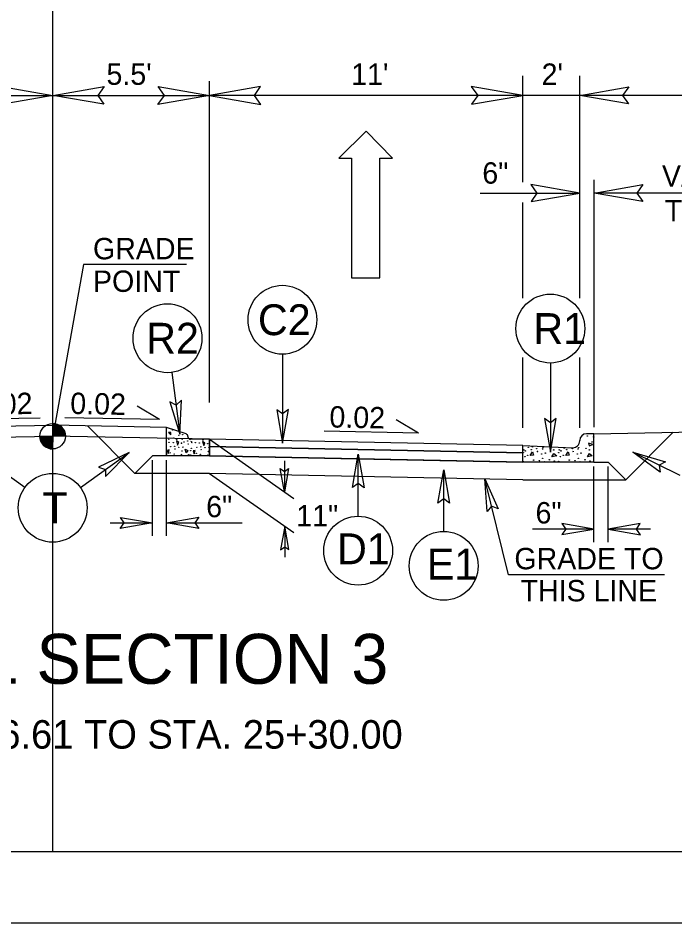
# Model space of a CAD drawing. Extents: x 1487909 to 1489267, y 497866 to 499814.
# Drawn here: x 1488973.75 to 1488996.8, y 498227.52 to 498259.26 of the extents above; entities that cross this region are included whole.
import ezdxf

# ---------------------------------------------------------------- set-up
doc = ezdxf.new("R2010")
doc.units = 0
for name, color, linetype in [('Old_Level_10', 7, 'Continuous'), ('Prop Dimension', 7, 'Continuous'), ('Prop Dimension Text', 7, 'Continuous'), ('Prop Lane Arrow CELL', 7, 'Continuous'), ('Prop Shade Light', 7, 'Continuous'), ('Prop Terminator CELL', 7, 'Continuous'), ('Scratch_Level_1', 7, 'Continuous'), ('Sheet Plot Border Outside CELL', 7, 'Continuous'), ('Sheet Typical CELL', 7, 'Continuous'), ('Typical Curb CELL', 7, 'Continuous'), ('Typical Detail Wedge2 CELL', 7, 'Continuous'), ('Typical Grade Point Symbol CELL', 7, 'Continuous'), ('Typical Hinge Slope Arterial CELL', 7, 'Continuous'), ('Typical ID Circle CELL', 7, 'Continuous'), ('Typical Pavement Slope CELL', 7, 'Continuous'), ('Typical Pavement Slope Information CELL', 7, 'Continuous'), ('Typical Terminator CELL', 7, 'Continuous'), ('Typical Text Grade Point CELL', 7, 'Continuous'), ('Typical Text ID Circle CELL', 7, 'Continuous')]:
    doc.layers.add(name, color=color, linetype=linetype)

msp = doc.modelspace()

# ---------------------------------------------------------------- linework, layer by layer
at = {"layer": 'Old_Level_10'}
for p, q in [((1488980.464, 498244.233), (1488980.464, 498243.899)), ((1488991.464, 498244.013), (1488980.464, 498244.233)), ((1488980.464, 498244.233), (1488980.464, 498244.233)), ((1488991.464, 498243.679), (1488991.464, 498244.013)), ((1488980.464, 498243.899), (1488987.964, 498243.749)), ((1488987.964, 498243.749), (1488991.464, 498243.679))]:
    msp.add_line(p, q, dxfattribs=at)
at = {"layer": 'Prop Dimension'}
for p, q in [((1488974.964, 498243.638), (1488974.964, 498259.111)), ((1488980.464, 498245.779), (1488980.464, 498257.045)), ((1488991.464, 498253.503), (1488991.464, 498257.235)), ((1488993.463, 498249.434), (1488993.463, 498257.235)), ((1488969.464, 498256.545), (1488974.964, 498256.545)), ((1488974.964, 498256.545), (1488980.464, 498256.545)), ((1488991.464, 498256.545), (1488980.464, 498256.545)), ((1488993.464, 498256.545), (1488991.464, 498256.545)), ((1489012.964, 498256.545), (1488993.464, 498256.545)), ((1488993.964, 498244.905), (1488993.964, 498253.586)), ((1488989.969, 498253.115), (1488993.464, 498253.115)), ((1489001.964, 498253.115), (1488993.964, 498253.115)), ((1488991.463, 498249.434), (1488991.463, 498252.793)), ((1488991.463, 498244.883), (1488991.463, 498247.353)), ((1488993.463, 498244.883), (1488993.463, 498247.353)), ((1488978.464, 498241.093), (1488978.464, 498243.747)), ((1488978.964, 498241.093), (1488978.964, 498243.747)), ((1488993.963, 498240.873), (1488993.963, 498243.527)), ((1488994.463, 498240.873), (1488994.463, 498243.527)), ((1488990.963, 498239.729), (1488990.13, 498243.093)), ((1488976.977, 498241.553), (1488978.464, 498241.553)), ((1488978.964, 498241.553), (1488981.612, 498241.553)), ((1488993.963, 498241.333), (1488991.802, 498241.333)), ((1488995.95, 498241.333), (1488994.463, 498241.333)), ((1488996.436, 498239.729), (1488990.963, 498239.729))]:
    msp.add_line(p, q, dxfattribs=at)
at = {"layer": 'Prop Dimension Text'}
for p, q in [((1488976.051, 498250.615), (1488974.964, 498244.593)), ((1488979.666, 498250.615), (1488976.051, 498250.615))]:
    msp.add_line(p, q, dxfattribs=at)
at = {"layer": 'Prop Lane Arrow CELL'}
for p, q in [((1488985.962, 498255.291), (1488985.002, 498254.346)), ((1488986.892, 498254.346), (1488985.962, 498255.291)), ((1488985.002, 498254.346), (1488985.452, 498254.346)), ((1488985.452, 498254.346), (1488985.452, 498250.146)), ((1488986.442, 498250.146), (1488986.442, 498254.346)), ((1488986.442, 498254.346), (1488986.892, 498254.346)), ((1488985.452, 498250.146), (1488986.442, 498250.146))]:
    msp.add_line(p, q, dxfattribs=at)
at = {"layer": 'Prop Shade Light'}
for p, q in [((1488991.464, 498244.263), (1488980.464, 498244.483)), ((1488980.464, 498244.483), (1488980.464, 498244.233)), ((1488991.464, 498244.013), (1488991.464, 498244.263)), ((1488980.464, 498244.233), (1488991.464, 498244.013))]:
    msp.add_line(p, q, dxfattribs=at)
at = {"layer": 'Prop Terminator CELL'}
for points in [[(1488973.164, 498256.855), (1488974.964, 498256.545), (1488973.154, 498256.225), (1488973.384, 498256.545)], [(1488976.764, 498256.235), (1488974.964, 498256.545), (1488976.774, 498256.865), (1488976.544, 498256.545)], [(1488978.664, 498256.855), (1488980.464, 498256.545), (1488978.654, 498256.225), (1488978.884, 498256.545)], [(1488982.264, 498256.855), (1488980.464, 498256.545), (1488982.274, 498256.225), (1488982.044, 498256.545)], [(1488989.664, 498256.235), (1488991.464, 498256.545), (1488989.654, 498256.865), (1488989.884, 498256.545)], [(1488995.174, 498256.25), (1488993.464, 498256.545), (1488995.183, 498256.849), (1488994.965, 498256.545)], [(1488991.754, 498252.82), (1488993.464, 498253.115), (1488991.744, 498253.419), (1488991.963, 498253.115)], [(1488995.674, 498252.82), (1488993.964, 498253.115), (1488995.683, 498253.419), (1488995.465, 498253.115)], [(1488990.212, 498241.954), (1488990.13, 498243.093), (1488990.596, 498242.043), (1488990.367, 498242.134)], [(1488977.339, 498241.746), (1488978.464, 498241.553), (1488977.333, 498241.353), (1488977.476, 498241.553)], [(1488980.089, 498241.359), (1488978.964, 498241.553), (1488980.095, 498241.753), (1488979.951, 498241.553)], [(1488992.838, 498241.139), (1488993.963, 498241.333), (1488992.832, 498241.533), (1488992.976, 498241.333)], [(1488995.588, 498241.526), (1488994.463, 498241.333), (1488995.594, 498241.133), (1488995.451, 498241.333)]]:
    msp.add_lwpolyline(points, close=True, dxfattribs=at)
at = {"layer": 'Scratch_Level_1'}
msp.add_line((1488974.964, 498230.02), (1488974.964, 498335.02), dxfattribs=at)
at = {"layer": 'Sheet Plot Border Outside CELL'}
msp.add_lwpolyline([(1489051.664, 498337.52), (1488883.264, 498337.52), (1488883.264, 498227.52), (1489051.664, 498227.52)], close=True, dxfattribs=at)
at = {"layer": 'Sheet Typical CELL'}
msp.add_lwpolyline([(1489049.964, 498335.02), (1488899.964, 498335.02), (1488899.964, 498230.02), (1489049.964, 498230.02)], close=True, dxfattribs=at)
at = {"layer": 'Typical Curb CELL'}
for p, q in [((1488978.964, 498243.899), (1488978.964, 498244.899)), ((1488979.65, 498244.671), (1488978.964, 498244.899)), ((1488979.111, 498244.728), (1488979.025, 498244.728)), ((1488979.025, 498244.728), (1488979.106, 498244.641)), ((1488979.106, 498244.641), (1488979.111, 498244.728)), ((1488979.714, 498244.576), (1488979.714, 498244.582)), ((1488993.963, 498244.679), (1488993.703, 498244.679)), ((1488993.963, 498243.679), (1488993.963, 498244.679)), ((1488979.309, 498244.425), (1488979.35, 498244.275)), ((1488979.391, 498244.366), (1488979.309, 498244.425)), ((1488979.35, 498244.275), (1488979.391, 498244.366)), ((1488980.464, 498244.483), (1488979.807, 498244.483)), ((1488980.228, 498244.409), (1488980.27, 498244.261)), ((1488980.31, 498244.351), (1488980.228, 498244.409)), ((1488980.27, 498244.261), (1488980.31, 498244.351)), ((1488980.464, 498244.483), (1488980.464, 498243.899)), ((1488980.464, 498243.899), (1488980.464, 498244.476)), ((1488991.464, 498243.679), (1488991.464, 498244.263)), ((1488991.464, 498244.263), (1488993.214, 498244.19)), ((1488993.463, 498244.429), (1488993.463, 498244.44)), ((1488993.773, 498244.346), (1488993.789, 498244.255)), ((1488993.927, 498244.301), (1488993.773, 498244.346)), ((1488993.789, 498244.255), (1488993.927, 498244.301)), ((1488979.052, 498244.109), (1488978.979, 498244.095)), ((1488978.979, 498244.095), (1488979.016, 498243.986)), ((1488979.016, 498243.986), (1488979.052, 498244.109)), ((1488979.617, 498244.136), (1488979.707, 498244.086)), ((1488979.648, 498244.005), (1488979.617, 498244.136)), ((1488979.707, 498244.086), (1488979.648, 498244.005)), ((1488979.971, 498244.093), (1488979.899, 498244.079)), ((1488979.899, 498244.079), (1488979.935, 498243.971)), ((1488979.935, 498243.971), (1488979.971, 498244.093)), ((1488991.724, 498243.919), (1488991.81, 498244.039)), ((1488991.81, 498244.039), (1488991.845, 498243.925)), ((1488992.489, 498243.868), (1488992.552, 498243.982)), ((1488992.552, 498243.982), (1488992.655, 498243.907)), ((1488992.974, 498243.919), (1488993.059, 498244.039)), ((1488993.059, 498244.039), (1488993.094, 498243.925)), ((1488993.738, 498243.868), (1488993.801, 498243.982)), ((1488993.801, 498243.982), (1488993.904, 498243.907)), ((1488980.464, 498243.899), (1488978.964, 498243.899)), ((1488993.963, 498243.679), (1488991.464, 498243.679)), ((1488991.845, 498243.925), (1488991.724, 498243.919)), ((1488992.655, 498243.907), (1488992.489, 498243.868)), ((1488993.094, 498243.925), (1488992.974, 498243.919)), ((1488993.904, 498243.907), (1488993.738, 498243.868))]:
    msp.add_line(p, q, dxfattribs=at)
for centre, radius in [((1488979.174, 498244.813), 0.00635), ((1488979.391, 498244.624), 0.00635), ((1488979.526, 498244.646), 0.00635), ((1488993.733, 498244.603), 0.00802), ((1488993.95, 498244.569), 0.00802), ((1488979.039, 498244.488), 0.00635), ((1488979.047, 498244.38), 0.00635), ((1488979.197, 498244.366), 0.00635), ((1488979.201, 498244.529), 0.00635), ((1488979.319, 498244.479), 0.00635), ((1488979.486, 498244.348), 0.00635), ((1488979.508, 498244.484), 0.00635), ((1488979.576, 498244.393), 0.00635), ((1488979.698, 498244.42), 0.00635), ((1488979.721, 498244.321), 0.00635), ((1488979.834, 498244.398), 0.00635), ((1488979.849, 498244.369), 0.00635), ((1488979.967, 498244.364), 0.00635), ((1488980.116, 498244.351), 0.00635), ((1488980.238, 498244.463), 0.00635), ((1488980.405, 498244.332), 0.00635), ((1488993.898, 498244.387), 0.00802), ((1488979.084, 498244.009), 0.00635), ((1488979.106, 498244.222), 0.00635), ((1488979.228, 498243.969), 0.00635), ((1488979.242, 498244.235), 0.00635), ((1488979.255, 498244.14), 0.00635), ((1488979.391, 498244.204), 0.00635), ((1488979.49, 498243.951), 0.00635), ((1488979.504, 498244.073), 0.00635), ((1488979.535, 498244.208), 0.00635), ((1488979.734, 498243.946), 0.00635), ((1488979.811, 498244.086), 0.00635), ((1488979.811, 498243.933), 0.00635), ((1488979.827, 498244.165), 0.00635), ((1488980.003, 498243.994), 0.00635), ((1488980.025, 498244.206), 0.00635), ((1488980.147, 498243.953), 0.00635), ((1488980.161, 498244.22), 0.00635), ((1488980.174, 498244.125), 0.00635), ((1488980.31, 498244.188), 0.00635), ((1488980.409, 498243.935), 0.00635), ((1488980.423, 498244.057), 0.00635), ((1488980.455, 498244.192), 0.00635), ((1488991.48, 498244.016), 0.00802), ((1488991.497, 498244.113), 0.00802), ((1488991.553, 498244.079), 0.00802), ((1488991.662, 498244.204), 0.00802), ((1488991.759, 498244.119), 0.00802), ((1488991.804, 498244.221), 0.00802), ((1488991.953, 498244.158), 0.00802), ((1488991.981, 498244.056), 0.00802), ((1488992.13, 498243.971), 0.00802), ((1488992.158, 498244.142), 0.00802), ((1488992.175, 498244.192), 0.00802), ((1488992.256, 498243.999), 0.00802), ((1488992.432, 498244.164), 0.00802), ((1488992.552, 498244.113), 0.00802), ((1488992.729, 498244.016), 0.00802), ((1488992.746, 498244.113), 0.00802), ((1488992.802, 498244.079), 0.00802), ((1488992.911, 498244.173), 0.00802), ((1488993.008, 498244.119), 0.00802), ((1488993.202, 498244.158), 0.00802), ((1488993.23, 498244.056), 0.00802), ((1488993.379, 498243.971), 0.00802), ((1488993.407, 498244.142), 0.00802), ((1488993.425, 498244.192), 0.00802), ((1488993.505, 498243.999), 0.00802), ((1488993.681, 498244.164), 0.00802), ((1488993.801, 498244.113), 0.00802), ((1488991.474, 498243.708), 0.00802), ((1488991.537, 498243.874), 0.00802), ((1488991.633, 498243.919), 0.00802), ((1488991.685, 498243.685), 0.00802), ((1488991.844, 498243.754), 0.00802), ((1488992.05, 498243.731), 0.00802), ((1488992.164, 498243.817), 0.00802), ((1488992.221, 498243.702), 0.00802), ((1488992.398, 498243.765), 0.00802), ((1488992.569, 498243.725), 0.00802), ((1488992.723, 498243.708), 0.00802), ((1488992.786, 498243.874), 0.00802), ((1488992.882, 498243.919), 0.00802), ((1488992.934, 498243.685), 0.00802), ((1488993.093, 498243.754), 0.00802), ((1488993.299, 498243.731), 0.00802), ((1488993.413, 498243.817), 0.00802), ((1488993.47, 498243.702), 0.00802), ((1488993.647, 498243.765), 0.00802), ((1488993.818, 498243.725), 0.00802)]:
    msp.add_circle(centre, radius, dxfattribs=at)
for centre, radius, start, end in [((1488979.62, 498244.582), 0.0937, 360, 71.565), ((1488979.807, 498244.576), 0.0937, 180, 270), ((1488993.703, 498244.44), 0.24, 90, 180), ((1488993.224, 498244.429), 0.24, 267.6155, 0), ((1488978.998, 498243.905), 0.00635, 27.0386, 154.2416)]:
    msp.add_arc(centre, radius, start, end, dxfattribs=at)
at = {"layer": 'Typical Detail Wedge2 CELL'}
for p, q in [((1488980.464, 498244.483), (1488983.428, 498242.407)), ((1488983.096, 498243.723), (1488983.096, 498242.639)), ((1488980.464, 498243.286), (1488983.428, 498241.211)), ((1488983.107, 498241.435), (1488983.107, 498240.351))]:
    msp.add_line(p, q, dxfattribs=at)
at = {"layer": 'Typical Grade Point Symbol CELL'}
for p, q in [((1488974.964, 498244.593), (1488974.964, 498245.04)), ((1488974.516, 498244.593), (1488974.964, 498244.593)), ((1488974.963, 498244.145), (1488974.964, 498244.593)), ((1488974.964, 498244.593), (1488974.963, 498244.145)), ((1488975.411, 498244.593), (1488974.964, 498244.593))]:
    msp.add_line(p, q, dxfattribs=at)
for points in [[(1488974.968, 498245.04), (1488974.968, 498245.04), (1488974.968, 498244.593)], [(1488974.977, 498245.04), (1488974.977, 498244.593)], [(1488974.986, 498245.039), (1488974.986, 498244.593)], [(1488974.994, 498245.039), (1488974.994, 498244.593)], [(1488975.003, 498245.038), (1488975.003, 498244.593)], [(1488975.012, 498245.037), (1488975.012, 498244.593)], [(1488975.021, 498245.036), (1488975.021, 498244.593)], [(1488975.03, 498245.035), (1488975.03, 498244.593)], [(1488975.039, 498245.034), (1488975.039, 498244.593)], [(1488975.048, 498245.032), (1488975.048, 498244.593)], [(1488975.057, 498245.03), (1488975.057, 498244.593)], [(1488975.066, 498245.028), (1488975.066, 498244.593)], [(1488975.075, 498245.026), (1488975.075, 498244.593)], [(1488975.084, 498245.023), (1488975.084, 498244.593)], [(1488975.093, 498245.021), (1488975.093, 498244.593)], [(1488975.102, 498245.018), (1488975.102, 498244.593)], [(1488975.111, 498245.015), (1488975.111, 498244.593)], [(1488975.12, 498245.012), (1488975.12, 498244.593)], [(1488975.129, 498245.008), (1488975.129, 498244.593)], [(1488975.138, 498245.004), (1488975.138, 498244.593)], [(1488975.147, 498245), (1488975.147, 498244.593)], [(1488975.156, 498244.996), (1488975.156, 498244.593)], [(1488975.165, 498244.992), (1488975.165, 498244.593)], [(1488975.173, 498244.987), (1488975.173, 498244.593)], [(1488975.182, 498244.983), (1488975.182, 498244.593)], [(1488975.191, 498244.978), (1488975.191, 498244.593)], [(1488975.2, 498244.973), (1488975.2, 498244.593)], [(1488975.209, 498244.967), (1488975.209, 498244.593)], [(1488975.218, 498244.961), (1488975.218, 498244.593)], [(1488975.227, 498244.954), (1488975.227, 498244.593)], [(1488975.236, 498244.948), (1488975.236, 498244.593)], [(1488975.245, 498244.941), (1488975.245, 498244.593)], [(1488975.254, 498244.933), (1488975.254, 498244.593)], [(1488975.263, 498244.925), (1488975.263, 498244.593)], [(1488975.272, 498244.917), (1488975.272, 498244.593)], [(1488975.281, 498244.908), (1488975.281, 498244.593)], [(1488975.29, 498244.899), (1488975.29, 498244.593)], [(1488974.518, 498244.593), (1488974.518, 498244.544)], [(1488974.527, 498244.593), (1488974.527, 498244.491)], [(1488974.536, 498244.593), (1488974.536, 498244.459)], [(1488974.545, 498244.593), (1488974.545, 498244.432)], [(1488974.554, 498244.593), (1488974.554, 498244.412)], [(1488974.563, 498244.593), (1488974.563, 498244.393)], [(1488974.572, 498244.593), (1488974.572, 498244.376)], [(1488974.581, 498244.593), (1488974.581, 498244.36)], [(1488974.59, 498244.593), (1488974.59, 498244.346)], [(1488974.599, 498244.593), (1488974.599, 498244.333)], [(1488974.608, 498244.593), (1488974.608, 498244.321)], [(1488974.616, 498244.593), (1488974.616, 498244.31)], [(1488974.625, 498244.593), (1488974.625, 498244.299)], [(1488974.634, 498244.593), (1488974.634, 498244.289)], [(1488974.643, 498244.593), (1488974.643, 498244.279)], [(1488974.652, 498244.593), (1488974.652, 498244.27)], [(1488974.661, 498244.593), (1488974.661, 498244.262)], [(1488974.67, 498244.593), (1488974.67, 498244.254)], [(1488974.679, 498244.593), (1488974.679, 498244.247)], [(1488974.688, 498244.593), (1488974.688, 498244.24)], [(1488974.697, 498244.593), (1488974.697, 498244.233)], [(1488974.706, 498244.593), (1488974.706, 498244.227)], [(1488974.715, 498244.593), (1488974.715, 498244.221)], [(1488974.724, 498244.593), (1488974.724, 498244.215)], [(1488974.733, 498244.593), (1488974.733, 498244.209)], [(1488974.742, 498244.593), (1488974.742, 498244.204)], [(1488974.751, 498244.593), (1488974.751, 498244.199)], [(1488974.76, 498244.593), (1488974.76, 498244.194)], [(1488974.769, 498244.593), (1488974.769, 498244.19)], [(1488974.778, 498244.593), (1488974.778, 498244.186)], [(1488974.787, 498244.593), (1488974.787, 498244.182)], [(1488974.795, 498244.593), (1488974.795, 498244.178)], [(1488974.804, 498244.593), (1488974.804, 498244.174)], [(1488974.813, 498244.593), (1488974.813, 498244.171)], [(1488974.822, 498244.593), (1488974.822, 498244.168)], [(1488974.831, 498244.593), (1488974.831, 498244.165)], [(1488974.84, 498244.593), (1488974.84, 498244.163)], [(1488974.849, 498244.593), (1488974.849, 498244.16)], [(1488974.858, 498244.593), (1488974.858, 498244.158)], [(1488974.867, 498244.593), (1488974.867, 498244.156)], [(1488974.876, 498244.593), (1488974.876, 498244.154)], [(1488974.885, 498244.593), (1488974.885, 498244.152)], [(1488974.894, 498244.593), (1488974.894, 498244.151)], [(1488974.903, 498244.593), (1488974.903, 498244.149)], [(1488974.912, 498244.593), (1488974.912, 498244.148)], [(1488974.921, 498244.593), (1488974.921, 498244.147)], [(1488974.93, 498244.593), (1488974.93, 498244.146)], [(1488974.939, 498244.593), (1488974.939, 498244.146)], [(1488974.948, 498244.593), (1488974.948, 498244.145)], [(1488974.957, 498244.593), (1488974.957, 498244.145), (1488974.957, 498244.145)], [(1488975.299, 498244.889), (1488975.299, 498244.593)], [(1488975.308, 498244.878), (1488975.308, 498244.593)], [(1488975.317, 498244.867), (1488975.317, 498244.593)], [(1488975.326, 498244.855), (1488975.326, 498244.593)], [(1488975.335, 498244.842), (1488975.335, 498244.593)], [(1488975.344, 498244.828), (1488975.344, 498244.593)], [(1488975.352, 498244.813), (1488975.352, 498244.593)], [(1488975.361, 498244.798), (1488975.361, 498244.593)], [(1488975.37, 498244.779), (1488975.37, 498244.593)], [(1488975.379, 498244.758), (1488975.379, 498244.593)], [(1488975.388, 498244.733), (1488975.388, 498244.593)], [(1488975.397, 498244.702), (1488975.397, 498244.593)], [(1488975.406, 498244.656), (1488975.406, 498244.593)]]:
    msp.add_lwpolyline(points, dxfattribs=at)
msp.add_circle((1488974.963, 498244.593), 0.448, dxfattribs=at)
for start, end in [(359.9905, 89.9905), (179.9905, 269.9905)]:
    msp.add_arc((1488974.963, 498244.593), 0.448, start, end, dxfattribs=at)
at = {"layer": 'Typical ID Circle CELL'}
for p, q in [((1488983.028, 498247.469), (1488983.028, 498244.346)), ((1488992.431, 498247.16), (1488992.431, 498244.036)), ((1488979.151, 498246.83), (1488979.432, 498244.665)), ((1488973.985, 498242.79), (1488972.28, 498244.025)), ((1488975.942, 498242.79), (1488977.647, 498244.025)), ((1488985.684, 498241.787), (1488985.684, 498243.965)), ((1488996.988, 498243.209), (1488995.331, 498244.033)), ((1488988.688, 498241.252), (1488988.688, 498243.418))]:
    msp.add_line(p, q, dxfattribs=at)
for centre in [(1488983.028, 498248.677), (1488992.431, 498248.368), (1488978.995, 498248.029), (1488974.964, 498242.082), (1488985.684, 498240.579), (1488988.688, 498240.044)]:
    msp.add_circle(centre, 1.208, dxfattribs=at)
at = {"layer": 'Typical Pavement Slope CELL'}
for p, q in [((1488970.963, 498244.899), (1488974.964, 498244.979)), ((1488978.964, 498244.899), (1488974.964, 498244.979)), ((1488976.182, 498244.955), (1488977.851, 498243.286)), ((1488993.963, 498244.679), (1489012.963, 498245.059)), ((1488969.464, 498244.483), (1488974.964, 498244.593)), ((1488980.464, 498244.483), (1488974.964, 498244.593)), ((1488996.745, 498244.735), (1488995.077, 498243.066)), ((1488991.464, 498244.263), (1488980.464, 498244.483)), ((1488991.464, 498244.013), (1488980.464, 498244.233)), ((1488978.464, 498243.899), (1488977.851, 498243.286)), ((1488978.964, 498243.899), (1488978.464, 498243.899)), ((1488991.464, 498243.679), (1488980.464, 498243.899)), ((1488993.963, 498243.679), (1488994.463, 498243.679)), ((1488994.463, 498243.679), (1488995.077, 498243.066)), ((1488980.464, 498243.286), (1488977.851, 498243.286)), ((1488991.464, 498243.066), (1488980.464, 498243.286)), ((1488991.464, 498243.066), (1488995.077, 498243.066))]:
    msp.add_line(p, q, dxfattribs=at)
at = {"layer": 'Typical Pavement Slope Information CELL'}
for p, q in [((1488978.712, 498245.173), (1488977.929, 498245.646)), ((1488971.215, 498245.173), (1488974.531, 498245.239)), ((1488978.712, 498245.173), (1488975.396, 498245.239)), ((1488987.808, 498244.698), (1488987.025, 498245.172)), ((1488987.808, 498244.698), (1488984.492, 498244.765))]:
    msp.add_line(p, q, dxfattribs=at)
at = {"layer": 'Typical Terminator CELL'}
for points in [[(1488979.081, 498245.801), (1488979.432, 498244.665), (1488979.487, 498245.86), (1488979.3, 498245.685)], [(1488982.827, 498245.518), (1488983.028, 498244.346), (1488983.237, 498245.524), (1488983.028, 498245.374)], [(1488992.229, 498245.208), (1488992.431, 498244.036), (1488992.64, 498245.215), (1488992.431, 498245.065)], [(1488976.816, 498243.174), (1488977.647, 498244.025), (1488976.571, 498243.503), (1488976.814, 498243.422)], [(1488985.482, 498242.793), (1488985.684, 498243.965), (1488985.892, 498242.787), (1488985.684, 498242.936)], [(1488996.29, 498243.331), (1488995.331, 498244.033), (1488996.478, 498243.695), (1488996.252, 498243.575)], [(1488983.237, 498243.459), (1488983.096, 498242.639), (1488982.95, 498243.464), (1488983.096, 498243.359)], [(1488988.486, 498242.247), (1488988.688, 498243.418), (1488988.896, 498242.24), (1488988.688, 498242.39)], [(1488983.248, 498240.615), (1488983.107, 498241.435), (1488982.961, 498240.611), (1488983.107, 498240.716)]]:
    msp.add_lwpolyline(points, close=True, dxfattribs=at)

# ---------------------------------------------------------------- texts
at = {"layer": 'Prop Dimension Text'}
for s, p in [("5.5'", (1488976.853, 498256.918)), ("11'", (1488985.441, 498256.918)), ("2'", (1488992.125, 498256.918)), ('6"', (1488990.044, 498253.451)), ("VAR. 2'", (1488996.348, 498253.349)), ("TO 8'", (1488996.448, 498252.13)), ('6"', (1488980.352, 498241.751)), ('11"', (1488983.514, 498241.428)), ('6"', (1488991.912, 498241.532)), ('GRADE TO', (1488991.169, 498239.924)), ('THIS LINE', (1488991.387, 498238.799))]:
    msp.add_text(s, height=0.75, dxfattribs=at).set_placement(p)
at = {"layer": 'Typical Hinge Slope Arterial CELL'}
msp.add_text('FROM -L- STA. 24+76.61 TO STA. 25+30.00', height=1, dxfattribs=at).set_placement((1488960.42, 498233.633))
at = {"layer": 'Typical Pavement Slope CELL'}
msp.add_text('TYPICAL SECTION 3', height=1.75, dxfattribs=at).set_placement((1488963.989, 498235.908))
at = {"layer": 'Typical Pavement Slope Information CELL'}
for rotation, p in [(1.1457, (1488972.313, 498245.334)), (358.8543, (1488975.576, 498245.375)), (358.8543, (1488984.672, 498244.9))]:
    msp.add_text('0.02', height=0.75, rotation=rotation, dxfattribs=at).set_placement(p)
at = {"layer": 'Typical Text Grade Point CELL'}
for s, p in [('GRADE', (1488976.379, 498250.797)), ('POINT', (1488976.379, 498249.655))]:
    msp.add_text(s, height=0.75, dxfattribs=at).set_placement(p)
at = {"layer": 'Typical Text ID Circle CELL'}
for s, height, p in [('C2', 1.0817, (1488982.169, 498248.137)), ('R1', 1.0817, (1488991.838, 498247.827)), ('R2', 1.0817, (1488978.247, 498247.488)), ('T', 1.082, (1488974.608, 498241.541)), ('D1', 1.0817, (1488984.946, 498240.101)), ('E1', 1.0817, (1488988.096, 498239.565))]:
    msp.add_text(s, height=height, dxfattribs=at).set_placement(p)

doc.saveas('drawing.dxf')
